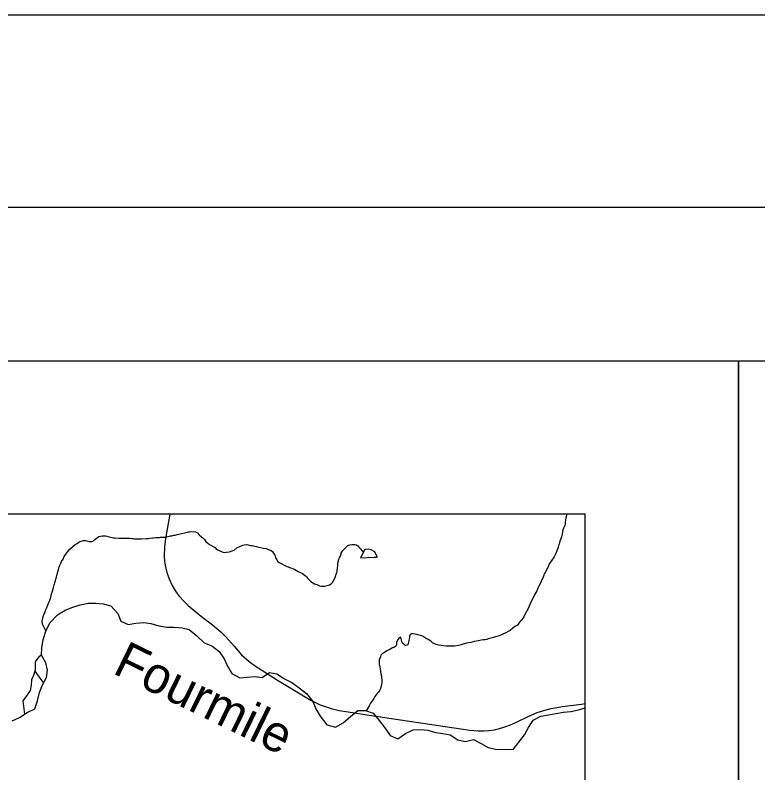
# Model space of a CAD drawing. Extents: x 0 to 39.3, y -3.9 to 22.
# Drawn here: x 7.215 to 9.15, y 20.026 to 22 of the extents above; entities that cross this region are included whole.
import ezdxf

# ---------------------------------------------------------------- set-up
doc = ezdxf.new("R2010")
doc.units = 0
for name, color, linetype in [('GM_X_Corporation', 7, 'Continuous'), ('GM_X_Minor_Lake', 7, 'Continuous'), ('GM_X_Minor_River', 7, 'Continuous'), ('GM_X_Minor_River_Text', 7, 'Continuous'), ('GM_X_Rail_Line', 7, 'Continuous'), ('SH_Border', 7, 'Continuous'), ('SH_Cut_Line', 7, 'Continuous'), ('SH_Data', 7, 'Continuous'), ('SH_Text', 7, 'Continuous')]:
    doc.layers.add(name, color=color, linetype=linetype)

msp = doc.modelspace()

# ---------------------------------------------------------------- linework, layer by layer
at = {"layer": 'GM_X_Corporation'}
msp.add_lwpolyline([(8.7, 17.1372), (8.7, 20.7), (3.278, 20.7)], dxfattribs=at)
at = {"layer": 'GM_X_Minor_Lake'}
for points in [[(8.1227, 20.6012), (8.1151, 20.5866), (8.1508, 20.5879), (8.158, 20.5878), (8.1577, 20.5904), (8.1526, 20.6023), (8.1424, 20.607)], [(8.1424, 20.607), (8.1352, 20.6091), (8.128, 20.608), (8.1245, 20.6066), (8.1227, 20.6012)]]:
    msp.add_lwpolyline(points, dxfattribs=at)
at = {"layer": 'GM_X_Minor_River'}
for points in [[(8.6522, 20.7), (8.6516, 20.6979), (8.6508, 20.6942), (8.65, 20.69), (8.6491, 20.6847), (8.6483, 20.6798), (8.6479, 20.6763), (8.647, 20.6703), (8.6435, 20.6639), (8.6419, 20.659), (8.641, 20.6548), (8.6402, 20.6484), (8.6385, 20.6408), (8.6373, 20.6359), (8.6345, 20.6298), (8.6325, 20.6223), (8.6313, 20.6189), (8.6297, 20.6136), (8.6269, 20.6049), (8.6237, 20.5977), (8.6221, 20.5943), (8.6198, 20.5887), (8.6139, 20.5804), (8.6097, 20.5748), (8.6069, 20.571), (8.6046, 20.5654), (8.6002, 20.5563), (8.5959, 20.5484), (8.5936, 20.5447), (8.5924, 20.5416), (8.59, 20.5337), (8.5876, 20.5296), (8.5848, 20.522)], [(7.2949, 20.396), (7.2858, 20.4136), (7.2852, 20.4212), (7.286, 20.425), (7.2881, 20.4333), (7.2908, 20.4405), (7.2928, 20.4447), (7.2944, 20.4492), (7.2948, 20.4522), (7.2984, 20.459), (7.3016, 20.4681), (7.3031, 20.4715), (7.3059, 20.4783), (7.3075, 20.4839), (7.31, 20.4923), (7.312, 20.4995), (7.3152, 20.5089), (7.316, 20.5131), (7.3164, 20.5165), (7.32, 20.5271), (7.3205, 20.5305), (7.3225, 20.5365), (7.3245, 20.5441), (7.3261, 20.5498), (7.3278, 20.5562), (7.3298, 20.5626), (7.3317, 20.5671), (7.3337, 20.5724), (7.3361, 20.5773), (7.3396, 20.5834), (7.3424, 20.5898), (7.3467, 20.5962), (7.3521, 20.6033), (7.3575, 20.6093), (7.3645, 20.6152), (7.371, 20.6208), (7.3768, 20.6238), (7.381, 20.6271), (7.3841, 20.6289), (7.3925, 20.6315), (7.3978, 20.6317), (7.4016, 20.6309), (7.4046, 20.6301), (7.4077, 20.6293), (7.4107, 20.6289), (7.4153, 20.6292), (7.4187, 20.6306), (7.4222, 20.6344), (7.4264, 20.6369), (7.4295, 20.6392), (7.4326, 20.6418), (7.4372, 20.6428), (7.4421, 20.6435), (7.4501, 20.6434), (7.4539, 20.6425), (7.4603, 20.6413), (7.4679, 20.6396), (7.4717, 20.6384), (7.4755, 20.6384), (7.485, 20.6374), (7.493, 20.6377), (7.496, 20.6376), (7.5021, 20.6379), (7.5089, 20.6378), (7.5127, 20.6373), (7.5196, 20.6368), (7.523, 20.6368), (7.5272, 20.6363), (7.5306, 20.6359), (7.5412, 20.6357), (7.5443, 20.636), (7.5561, 20.637), (7.5618, 20.6372), (7.5652, 20.6376), (7.5725, 20.6386), (7.5755, 20.6385), (7.5816, 20.6392), (7.585, 20.6395), (7.5911, 20.6398), (7.5941, 20.6401), (7.6006, 20.64), (7.6056, 20.6406), (7.6098, 20.6413), (7.6136, 20.642), (7.6201, 20.6438), (7.6235, 20.6441), (7.6285, 20.6456), (7.6319, 20.6459), (7.6368, 20.6473), (7.6452, 20.6491), (7.6487, 20.6498), (7.6559, 20.6519), (7.6601, 20.6526), (7.667, 20.654), (7.67, 20.6543), (7.6803, 20.6549), (7.6845, 20.6541), (7.6898, 20.6513), (7.6942, 20.6463), (7.7006, 20.6416), (7.7036, 20.6382)], [(7.7036, 20.6382), (7.7085, 20.6343), (7.7118, 20.6293), (7.7182, 20.6242), (7.7227, 20.6204), (7.7295, 20.6172), (7.7329, 20.6148), (7.7359, 20.6133), (7.7389, 20.6102), (7.7426, 20.6071), (7.7468, 20.6055), (7.7558, 20.6015), (7.7611, 20.6007), (7.7653, 20.601), (7.7726, 20.6024), (7.776, 20.6027), (7.7825, 20.6052), (7.7856, 20.6067), (7.7937, 20.6134), (7.7986, 20.6152), (7.8082, 20.6192), (7.812, 20.6203), (7.8189, 20.6209), (7.8284, 20.6189), (7.8329, 20.6184), (7.8394, 20.6168), (7.8435, 20.6163), (7.8496, 20.6143), (7.8575, 20.6127), (7.8621, 20.6118), (7.8681, 20.6106), (7.8753, 20.6086), (7.8821, 20.6058), (7.8859, 20.603), (7.8885, 20.5984), (7.8914, 20.5934), (7.8932, 20.5866), (7.8969, 20.5812), (7.8988, 20.5777), (7.9025, 20.5743), (7.9229, 20.5636), (7.9263, 20.5628), (7.9327, 20.5604), (7.9357, 20.5592), (7.9403, 20.558), (7.9436, 20.5557), (7.9523, 20.5506), (7.9561, 20.5494), (7.9636, 20.5454), (7.967, 20.5427), (7.9715, 20.54), (7.9745, 20.5369), (7.9767, 20.5338), (7.9793, 20.5307), (7.9849, 20.5253), (7.9883, 20.523), (7.9947, 20.519), (7.9977, 20.5179), (8.0012, 20.5167), (8.0042, 20.5155), (8.0083, 20.5139), (8.0125, 20.5127), (8.0174, 20.5126), (8.0209, 20.5129), (8.0247, 20.5136), (8.0281, 20.5143), (8.0342, 20.5165), (8.0381, 20.519), (8.0423, 20.522), (8.0451, 20.5284), (8.0494, 20.5379), (8.0526, 20.5465), (8.0538, 20.5503), (8.0542, 20.5533), (8.0547, 20.5598), (8.0556, 20.5662), (8.0561, 20.5727), (8.0585, 20.5822), (8.0593, 20.5856), (8.0641, 20.595), (8.0649, 20.5984), (8.0688, 20.6052), (8.0754, 20.6126), (8.0823, 20.6182), (8.0869, 20.6204), (8.0919, 20.6211), (8.0999, 20.6213), (8.1033, 20.6205), (8.1081, 20.6174), (8.1119, 20.6128), (8.1152, 20.6097), (8.1186, 20.6054), (8.1227, 20.6012)], [(8.5848, 20.522), (8.5793, 20.513), (8.5781, 20.5096), (8.5746, 20.5002), (8.5695, 20.4915), (8.5648, 20.4825), (8.5608, 20.4745), (8.5589, 20.4708), (8.5573, 20.4666), (8.5545, 20.4602), (8.5514, 20.4542), (8.5494, 20.45), (8.5478, 20.4463), (8.5431, 20.4391), (8.5407, 20.4331), (8.5384, 20.4301), (8.5353, 20.4241), (8.5322, 20.4218), (8.5291, 20.4185), (8.5237, 20.411), (8.5171, 20.4073), (8.5048, 20.3969), (8.4998, 20.3947), (8.4937, 20.391), (8.4879, 20.3884), (8.4848, 20.3866), (8.4802, 20.3847), (8.4764, 20.3837), (8.4703, 20.3819), (8.4669, 20.3808), (8.4577, 20.3783), (8.4547, 20.3772), (8.4474, 20.3751), (8.4443, 20.374), (8.439, 20.3729), (8.4352, 20.3726), (8.4295, 20.3716), (8.4226, 20.3705), (8.4176, 20.3695), (8.4115, 20.3685), (8.4081, 20.3681), (8.402, 20.3663), (8.3913, 20.3639), (8.3852, 20.3621), (8.3772, 20.3599), (8.3738, 20.3592), (8.3699, 20.3582), (8.3604, 20.3568), (8.357, 20.3565), (8.3536, 20.3566), (8.3505, 20.3562), (8.3475, 20.3563), (8.3433, 20.3564), (8.3384, 20.3568), (8.3315, 20.3573), (8.3255, 20.3582), (8.319, 20.3591), (8.3126, 20.3611), (8.308, 20.3623), (8.3028, 20.3654), (8.2979, 20.3693), (8.2934, 20.3717), (8.29, 20.3744), (8.287, 20.3756), (8.2821, 20.3787), (8.2787, 20.3814), (8.2745, 20.3834), (8.2647, 20.3859), (8.2613, 20.3867), (8.2571, 20.3879), (8.2522, 20.3887), (8.248, 20.3888), (8.2446, 20.387), (8.2426, 20.3824), (8.2422, 20.3794), (8.2413, 20.3752), (8.2405, 20.3699), (8.2397, 20.3669), (8.2392, 20.3635), (8.2373, 20.359), (8.2334, 20.3579), (8.2304, 20.3591), (8.2274, 20.3614), (8.2244, 20.3645), (8.223, 20.3683), (8.2219, 20.3722), (8.2208, 20.3756), (8.2194, 20.3794), (8.2159, 20.3783), (8.2128, 20.3742), (8.2089, 20.3671), (8.2085, 20.364), (8.2084, 20.3598), (8.2072, 20.3565), (8.2033, 20.3535), (8.1987, 20.3517), (8.1938, 20.3495), (8.1892, 20.3469), (8.1838, 20.3439), (8.1796, 20.3417), (8.1753, 20.3388)], [(7.2074, 20.162), (7.2264, 20.1704), (7.2461, 20.1837), (7.2659, 20.1932), (7.2731, 20.2141), (7.278, 20.2357), (7.286, 20.2555), (7.297, 20.2748), (7.2993, 20.2942), (7.2947, 20.3132), (7.2837, 20.3326), (7.2848, 20.352), (7.2879, 20.3736), (7.2955, 20.3979), (7.3065, 20.4177), (7.3255, 20.4378), (7.3452, 20.45), (7.3653, 20.4576), (7.3847, 20.464), (7.4052, 20.4682), (7.425, 20.4686), (7.4443, 20.4663), (7.4644, 20.4617), (7.4827, 20.4412), (7.4899, 20.4211), (7.5096, 20.4127), (7.5298, 20.4165), (7.5499, 20.4177), (7.5689, 20.415), (7.589, 20.409), (7.6099, 20.4063), (7.6293, 20.4055), (7.6498, 20.4044), (7.6687, 20.3998), (7.6881, 20.3835), (7.7071, 20.3653), (7.7272, 20.3569), (7.7466, 20.3425), (7.7595, 20.3231), (7.7682, 20.3041), (7.78, 20.2851), (7.8005, 20.2737), (7.8199, 20.2756), (7.8393, 20.2771), (7.8582, 20.2749), (7.8776, 20.2882), (7.8966, 20.2847), (7.9171, 20.2714), (7.9361, 20.2616), (7.9551, 20.2475), (7.9744, 20.2335), (7.9908, 20.2122), (7.9988, 20.1932), (8.0094, 20.1742), (8.0272, 20.1514), (8.05, 20.145), (8.0694, 20.1571), (8.0887, 20.1735), (8.1077, 20.1886), (8.1275, 20.189), (8.1476, 20.1822), (8.1632, 20.1632), (8.178, 20.1438), (8.1924, 20.1237), (8.2118, 20.1153), (8.2319, 20.1286), (8.2517, 20.1385), (8.2714, 20.1389), (8.2904, 20.1374), (8.3105, 20.1317), (8.3295, 20.129), (8.3489, 20.1252), (8.3686, 20.1127), (8.3884, 20.1077), (8.4096, 20.1134), (8.429, 20.1032), (8.448, 20.0925), (8.47, 20.0872), (8.4905, 20.088), (8.5129, 20.0872), (8.5274, 20.1062), (8.5425, 20.1252), (8.5524, 20.1442), (8.5649, 20.164), (8.5847, 20.1742), (8.6048, 20.1776), (8.6242, 20.1807), (8.6439, 20.1841), (8.6633, 20.1864), (8.6827, 20.1902), (8.7, 20.196)], [(7.2837, 20.3326), (7.2768, 20.3287), (7.2671, 20.3156), (7.2668, 20.2947), (7.2635, 20.2822), (7.2572, 20.2683), (7.2562, 20.2546), (7.2541, 20.2406), (7.2443, 20.2267), (7.2346, 20.2144), (7.2396, 20.1793)], [(8.1753, 20.3388), (8.1719, 20.3373), (8.168, 20.3328), (8.1668, 20.3279), (8.1652, 20.3249), (8.1636, 20.3211), (8.1632, 20.3154), (8.1638, 20.3089), (8.1649, 20.3047), (8.1656, 20.3017), (8.1663, 20.2963), (8.1669, 20.2918), (8.1673, 20.2883), (8.1676, 20.2853), (8.1687, 20.2811), (8.1694, 20.2781), (8.1697, 20.2742), (8.1704, 20.2697), (8.1707, 20.2659), (8.1706, 20.2628), (8.1694, 20.256), (8.1686, 20.253), (8.1677, 20.2488), (8.1666, 20.2458), (8.165, 20.2416), (8.1618, 20.2364), (8.1584, 20.233), (8.156, 20.2296), (8.1525, 20.2255), (8.1494, 20.2202), (8.1459, 20.2146), (8.1435, 20.2116), (8.1412, 20.2082), (8.1377, 20.2014), (8.1349, 20.1965), (8.1295, 20.1883)], [(7.2658, 20.2912), (7.2885, 20.26)]]:
    msp.add_lwpolyline(points, dxfattribs=at)
at = {"layer": 'GM_X_Rail_Line'}
msp.add_lwpolyline([(7.6182, 20.7), (7.6067, 20.6367), (7.6038, 20.6151), (7.6033, 20.591), (7.6044, 20.5771), (7.6067, 20.5626), (7.6102, 20.5484), (7.6159, 20.5315), (7.6239, 20.5148), (7.6331, 20.4994), (7.6416, 20.4878), (7.6542, 20.4734), (7.6655, 20.4625), (7.6961, 20.4375), (7.7295, 20.4121), (7.7409, 20.4028), (7.7511, 20.3936), (7.7637, 20.381), (7.7853, 20.3563), (7.805, 20.3341), (7.8244, 20.3168), (7.8412, 20.3043), (7.8646, 20.2893), (7.8987, 20.2681), (7.9706, 20.2242), (7.9858, 20.2156), (8.01, 20.2038), (8.0384, 20.1938), (8.0596, 20.1892), (8.0825, 20.185), (8.1379, 20.1764), (8.376, 20.1409), (8.4002, 20.1376), (8.4218, 20.1357), (8.436, 20.1357), (8.4495, 20.1365), (8.4637, 20.1388), (8.4768, 20.1418), (8.491, 20.1462), (8.5061, 20.1519), (8.521, 20.1587), (8.554, 20.1739), (8.5754, 20.1835), (8.5924, 20.1892), (8.6114, 20.1942), (8.6409, 20.1991), (8.6908, 20.2054), (8.7, 20.2072)], dxfattribs=at)
at = {"layer": 'SH_Border'}
msp.add_lwpolyline([(1.5, 21.5), (33.5, 21.5), (33.5, 0.5), (1.5, 0.5)], close=True, dxfattribs=at)
at = {"layer": 'SH_Cut_Line'}
msp.add_lwpolyline([(0, 0), (34, 0), (34, 22), (0, 22)], close=True, dxfattribs=at)
at = {"layer": 'SH_Data'}
msp.add_lwpolyline([(1.9, 21.1), (9.1, 21.1), (9.1, 13.9), (1.9, 13.9)], close=True, dxfattribs=at)
at = {"layer": 'SH_Text'}
msp.add_lwpolyline([(9.1, 21.1), (11.7047, 21.1), (11.7047, 13.9), (9.1, 13.9)], close=True, dxfattribs=at)

# ---------------------------------------------------------------- texts
at = {"layer": 'GM_X_Minor_River_Text'}
msp.add_text('Fourmile', height=0.09469, rotation=334.0117, dxfattribs=at).set_placement((7.4661, 20.2871))

doc.saveas('drawing.dxf')
